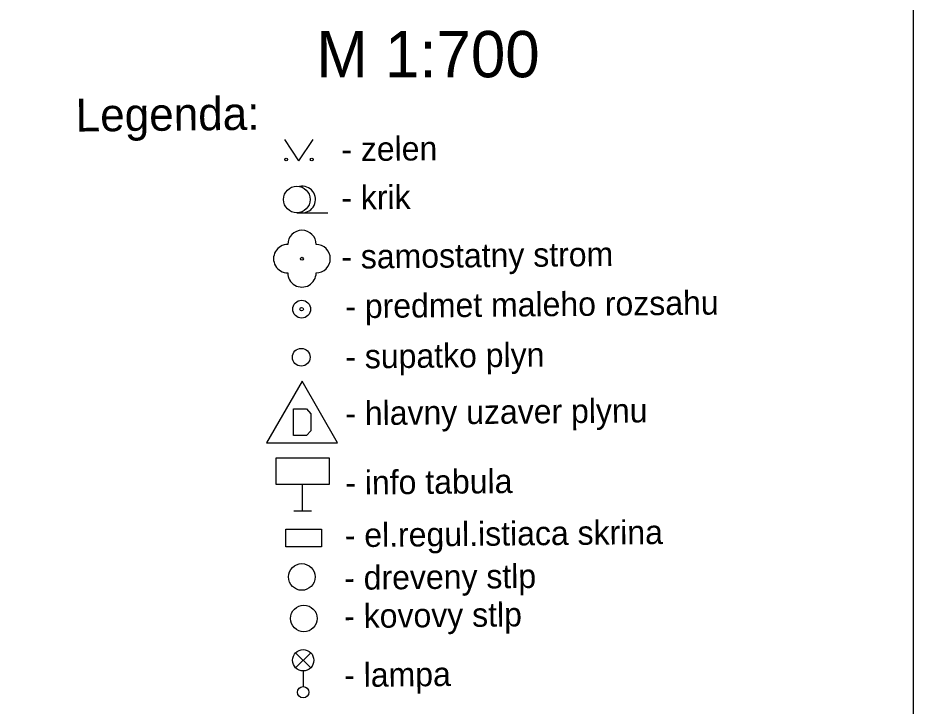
# Model space of a CAD drawing. Extents: x -400488 to -400124, y -1251493 to -1251223.
# Drawn here: x -400275.66 to -400250.43, y -1251279.74 to -1251260.37 of the extents above; entities that cross this region are included whole.
import ezdxf

# ---------------------------------------------------------------- set-up
doc = ezdxf.new("R2010")
doc.units = 0
for name, color, linetype in [('Level 3', 7, 'Continuous'), ('Level 32', 7, 'Continuous'), ('Level 36', 7, 'Continuous'), ('Level 50', 7, 'Continuous'), ('Level 53', 7, 'Continuous'), ('Level 54', 7, 'Continuous'), ('Level 60', 7, 'Continuous')]:
    doc.layers.add(name, color=color, linetype=linetype)

msp = doc.modelspace()

# ---------------------------------------------------------------- linework, layer by layer
at = {"layer": 'Level 3'}
msp.add_lwpolyline([(-400397.431, -1251233.087), (-400250.431, -1251233.087), (-400250.431, -1251440.987), (-400397.431, -1251440.987)], close=True, dxfattribs=at)
at = {"layer": 'Level 32'}
for p, q in [((-400267.632, -1251274.248), (-400267.632, -1251273.498)), ((-400267.882, -1251274.248), (-400267.382, -1251274.248))]:
    msp.add_line(p, q, dxfattribs=at)
msp.add_lwpolyline([(-400268.382, -1251272.748), (-400266.882, -1251272.748), (-400266.882, -1251273.498), (-400268.382, -1251273.498)], close=True, dxfattribs=at)
at = {"layer": 'Level 36'}
for p, q in [((-400267.737, -1251264.39), (-400268.137, -1251263.79)), ((-400267.737, -1251264.39), (-400267.337, -1251263.79)), ((-400267.796, -1251265.853), (-400266.921, -1251265.853))]:
    msp.add_line(p, q, dxfattribs=at)
for centre, radius in [((-400268.097, -1251264.35), 0.04), ((-400267.377, -1251264.35), 0.04), ((-400267.796, -1251265.478), 0.375), ((-400267.652, -1251267.144), 0.04)]:
    msp.add_circle(centre, radius, dxfattribs=at)
for centre, radius, start, end in [((-400267.646, -1251265.478), 0.375, 270, 101.537), ((-400267.652, -1251266.744), 0.4, 359.9998, 179.9998), ((-400268.052, -1251267.144), 0.4, 89.9998, 269.9998), ((-400267.252, -1251267.144), 0.4, 269.9998, 89.9998), ((-400267.652, -1251267.544), 0.4, 179.9998, 359.9998)]:
    msp.add_arc(centre, radius, start, end, dxfattribs=at)
at = {"layer": 'Level 50'}
msp.add_lwpolyline([(-400267.647, -1251270.593), (-400268.647, -1251272.325), (-400266.647, -1251272.325)], close=True, dxfattribs=at)
msp.add_lwpolyline([(-400267.892, -1251271.373), (-400267.526, -1251271.373), (-400267.402, -1251271.509), (-400267.402, -1251271.987), (-400267.526, -1251272.123), (-400267.892, -1251272.123), (-400267.892, -1251271.373)], dxfattribs=at)
msp.add_circle((-400267.671, -1251269.92), 0.25, dxfattribs=at)
at = {"layer": 'Level 53'}
for p, q in [((-400267.829, -1251278.663), (-400267.405, -1251278.239)), ((-400267.405, -1251278.239), (-400267.829, -1251278.663)), ((-400267.405, -1251278.663), (-400267.829, -1251278.239)), ((-400267.617, -1251278.751), (-400267.617, -1251279.191))]:
    msp.add_line(p, q, dxfattribs=at)
msp.add_lwpolyline([(-400268.103, -1251274.755), (-400267.103, -1251274.755), (-400267.103, -1251275.255), (-400268.103, -1251275.255)], close=True, dxfattribs=at)
for centre, radius in [((-400267.617, -1251278.451), 0.3), ((-400267.617, -1251279.351), 0.16)]:
    msp.add_circle(centre, radius, dxfattribs=at)
at = {"layer": 'Level 54'}
msp.add_circle((-400267.656, -1251276.105), 0.375, dxfattribs=at)
at = {"layer": 'Level 60'}
for centre, radius in [((-400267.66, -1251268.566), 0.25), ((-400267.66, -1251268.566), 0.05), ((-400267.598, -1251277.273), 0.375)]:
    msp.add_circle(centre, radius, dxfattribs=at)

# ---------------------------------------------------------------- texts
at = {"layer": 'Level 3'}
for s, height, rotation, p in [('M 1:700', 1.3022, 0.0072, (-400267.245, -1251262.037)), ('Legenda:', 0.9288, 0.5734, (-400274.024, -1251263.566)), ('- zelen', 0.6739, 0.5734, (-400266.54, -1251264.4)), ('- krik', 0.6739, 0.5734, (-400266.54, -1251265.763)), ('- samostatny strom', 0.67392, 0.5734, (-400266.54, -1251267.426)), ('- predmet maleho rozsahu', 0.67392, 0.5734, (-400266.427, -1251268.821)), ('- supatko plyn', 0.67392, 0.5734, (-400266.427, -1251270.238)), ('- hlavny uzaver plynu', 0.67392, 0.5734, (-400266.427, -1251271.836)), ('- info tabula', 0.67392, 0.5734, (-400266.427, -1251273.789)), ('- el.regul.istiaca skrina', 0.67392, 0.5734, (-400266.443, -1251275.267)), ('- dreveny stlp', 0.67392, 0.5734, (-400266.459, -1251276.468)), ('- kovovy stlp', 0.67392, 0.5734, (-400266.459, -1251277.545)), ('- lampa', 0.6739, 0.5734, (-400266.459, -1251279.205))]:
    msp.add_text(s, height=height, rotation=rotation, dxfattribs=at).set_placement(p)

doc.saveas('drawing.dxf')
